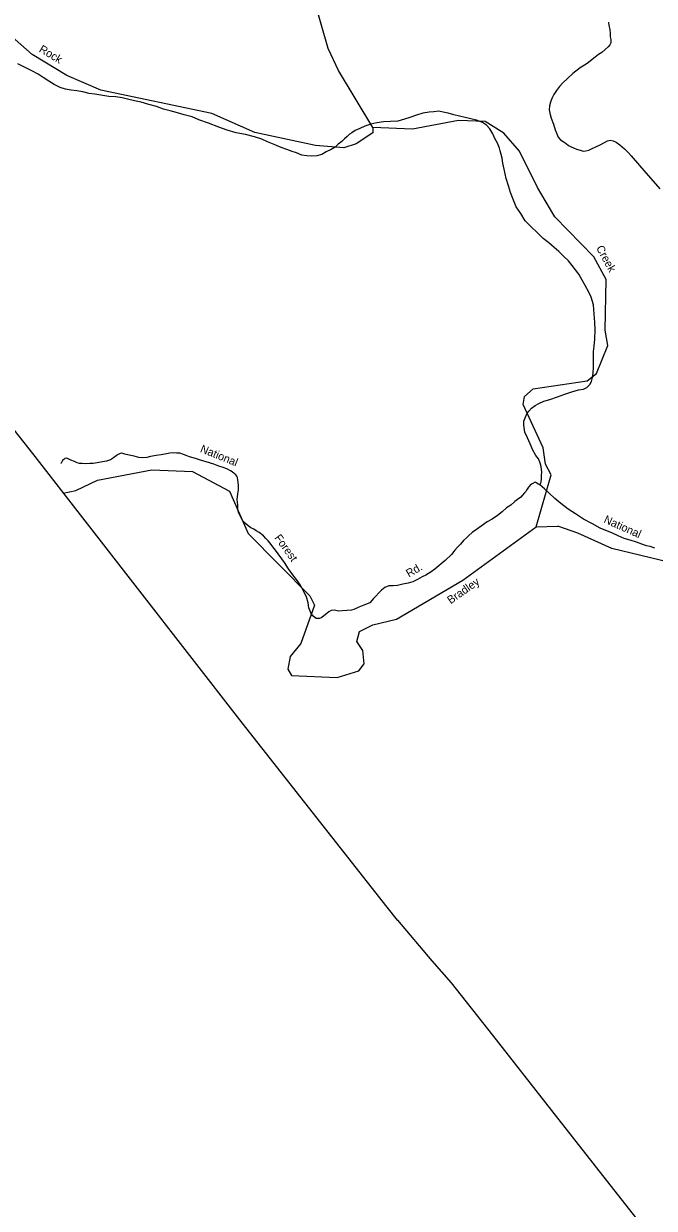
# Model space of a CAD drawing. Extents: x 884530 to 1028605, y 526725 to 653634.
# Drawn here: x 895600 to 900773, y 609593 to 619308 of the extents above; entities that cross this region are included whole.
import ezdxf

# ---------------------------------------------------------------- set-up
doc = ezdxf.new("R2010")
doc.units = 0
for name, color, linetype in [('Exist Boundary Political CountyLine', 7, 'Continuous'), ('Exist Hydrographic Creek Single Shore', 7, 'Continuous'), ('Exist Hydrographic Creek Single Shore Label', 7, 'Continuous'), ('Exist Hydrographic Misc Water Feature', 7, 'Continuous'), ('Exist Road Non-System Type 51', 7, 'Continuous'), ('Exist Road Secondary Type 51 Label', 7, 'Continuous'), ('Exist Road State Agency Type 41 National Forest', 7, 'Continuous')]:
    doc.layers.add(name, color=color, linetype=linetype)

msp = doc.modelspace()

# ---------------------------------------------------------------- linework, layer by layer
at = {"layer": 'Exist Boundary Political CountyLine'}
msp.add_lwpolyline([(884530.4, 629910.3), (884653.7, 629748.9), (884813.4, 629553.1), (885417.4, 628779.7), (886657.2, 627210), (887785.4, 625792.1), (888812.1, 624479.9), (890178.1, 622756.7), (890214.3, 622700.9), (890465.1, 622378.2), (892428, 619906.6), (893857.2, 618081), (895671, 615784.4), (897390.1, 613573.7), (898579.1, 612061.3), (898664.9, 611954.6), (898665.3, 611954.6), (898949, 611622.1), (899106.2, 611443), (899447, 611012.2), (899930.1, 610394.8), (900438.2, 609746.7), (902210.3, 607495.5)], dxfattribs=at)
at = {"layer": 'Exist Hydrographic Creek Single Shore'}
for points in [[(898465.1, 618456.6), (898463.7, 618413.9), (898326.6, 618321.5), (898225.5, 618290.7), (897992.7, 618308.5), (897496.4, 618416.9), (897143.6, 618571.7), (896233.3, 618763.8), (895954.4, 618884.3), (895668.8, 619054.1), (895483.1, 619218.6)], [(899802.8, 615181.9), (899927, 615608.4), (899880.2, 615694.7), (899860.4, 615829.6), (899698.2, 616184), (899709.3, 616249.4), (899778.2, 616313.7), (900222.7, 616380.2), (900299.7, 616437.8), (900391.8, 616668.9), (900371.3, 616794.1), (900378.5, 617210.6), (900277, 617396.4), (899955.7, 617724.5), (899814.4, 617963.5), (899667.1, 618261.8), (899539.1, 618408.8), (899384.4, 618507), (899167.7, 618514.6), (898789.9, 618443.5), (898465.1, 618456.6)], [(895924.1, 615459), (896028, 615480), (896206.3, 615565), (896651.3, 615647.9), (896984.3, 615634.7), (897286.9, 615474.4), (897441, 615126.7), (897947.3, 614614.5), (897986.1, 614538.3), (897874.5, 614225.5), (897787, 614118.9), (897766.5, 614014.4), (897798, 613961.3), (898172.6, 613947.1), (898349.6, 613999.4), (898393.5, 614057.6), (898380.9, 614166.1), (898333.6, 614242.5), (898353.5, 614324.1), (898463.8, 614377.7), (898657.2, 614423.1), (899202.8, 614743.5), (899802.8, 615181.9), (899982, 615187.2)], [(902911.8, 614462.4), (902755.5, 614527.9), (902511, 614680.5), (902374.1, 614807.9), (902276, 614862.4), (902083.3, 614836.7), (901772.2, 614990.6), (901628.8, 614944.3), (901447.9, 614793.7), (901437.7, 614744.7), (901256.1, 614567.9), (901131.5, 614580.2), (901010.3, 614684.3), (900901.2, 614890), (900424.7, 615002.6), (900145.3, 615129.2), (899982, 615187.2)]]:
    msp.add_lwpolyline(points, dxfattribs=at)
at = {"layer": 'Exist Hydrographic Misc Water Feature'}
msp.add_lwpolyline([(898465.1, 618456.6), (898182.3, 618924.9), (898097.3, 619103.9), (897934.9, 619668.2), (897896.5, 619987.3), (897919.4, 620603.7), (897871.1, 620870.5), (897795, 621065.6), (897412.2, 621539.3), (897312.3, 621767.7), (896946.4, 622247.6), (896395.3, 622901.8)], dxfattribs=at)
at = {"layer": 'Exist Road Non-System Type 51'}
for points in [[(900398.1, 619321.5), (900401.1, 619292.6), (900408, 619259.6), (900410, 619228.1), (900411.1, 619200.5), (900415.2, 619178.1)], [(900415.2, 619178.1), (900416, 619150.5), (900409.1, 619134.9), (900394, 619118.1), (900371.3, 619096.3), (900343.2, 619070.6), (900315.9, 619054.1), (900287, 619032.3), (900221, 618981.2), (900166.1, 618945.5), (900104.1, 618898.2), (900060, 618858.4), (900023.2, 618823.7), (899996, 618792.7), (899971.1, 618759.1), (899948.1, 618726.7), (899932, 618695.6), (899920.9, 618665.6), (899914.1, 618635.5), (899911.1, 618601.5), (899916.1, 618573.8), (899928.1, 618534.2), (899944.9, 618485.3), (899959, 618437.8), (899974.1, 618404.6), (899985.1, 618378.2), (900004, 618356.8), (900025, 618340.6), (900049, 618324.4), (900070, 618309.5), (900090.1, 618297.3), (900111.2, 618289), (900135, 618278), (900165, 618269.6), (900188.2, 618262.5), (900211.2, 618264.7), (900234.9, 618270.8), (900263.1, 618283.3), (900298.2, 618299.7), (900330, 618314.8), (900363.2, 618333.8), (900390, 618347.7), (900412.1, 618353.8), (900436, 618346.8), (900461, 618335.8), (900491.1, 618315.5), (900529.1, 618280.6), (900560.3, 618248.5), (900583.1, 618223.1), (900704.1, 618085.5), (900764.1, 618017.3), (900818.9, 617954.5)], [(898272.3, 618400.7), (898252.2, 618384), (898231.2, 618363.5), (898210.1, 618342.9), (898179.1, 618318.6), (898156, 618296.7), (898122.1, 618276.4), (898081, 618256.2), (898044.2, 618234.6), (898003.9, 618225), (897959.2, 618220.6), (897922.2, 618225.3), (897882.3, 618228.7), (897838, 618248), (897801.2, 618260.5), (897757.2, 618275.8), (897712.3, 618293.8), (897655, 618316), (897600.9, 618338), (897552.2, 618360), (897493.1, 618379.6), (897420, 618399.4), (897342.2, 618414.1), (897269.2, 618435.3), (897200.1, 618459), (897117, 618490.8), (897036.2, 618520), (896981.3, 618543.4), (896916.9, 618560.5), (896860.2, 618577.4), (896802.1, 618594.3), (896746.9, 618607.2), (896690.2, 618628), (896626.3, 618646.4), (896563, 618663.4), (896509.1, 618675), (896450, 618689.3), (896406.2, 618699.3), (896354.2, 618708.3), (896298.1, 618710.7), (896249.1, 618718.2), (896183, 618728.8), (896137.2, 618734.9), (896084.3, 618747.8), (896034.3, 618758), (895990.1, 618764.1), (895943.9, 618770.3), (895898.9, 618784.3), (895850.2, 618808.9), (895807.1, 618836), (895760.2, 618867.2), (895717.1, 618894.3), (895666.1, 618920.3), (895601.1, 618954.4), (895552.1, 618979)], [(899834.9, 615525), (899843.1, 615539.3), (899845, 615551), (899848.1, 615574.6), (899849, 615604.8), (899850.1, 615628.4), (899847.1, 615657.3), (899841.1, 615686.3), (899834.1, 615712.7), (899822.2, 615740.5), (899802, 615767.2), (899777, 615809.7), (899755.1, 615862.6), (899733.1, 615911.6), (899711.1, 615959.3), (899703, 616014.6), (899704, 616047.4), (899713.1, 616076.1), (899728.2, 616107.3), (899745, 616130.6), (899766.2, 616153.8), (899795.2, 616176.8), (899825, 616192), (899868.1, 616212.1), (899915, 616226.9), (899979.1, 616248), (900038.2, 616270.4), (900097, 616287.6), (900152.1, 616304.9), (900192, 616311.9), (900220.1, 616323.2), (900242.9, 616347.7), (900258.2, 616374.9), (900266.1, 616406.3), (900271.1, 616442.9), (900273, 616491.5), (900275.2, 616549.2), (900274.9, 616618.7), (900281.1, 616664.6), (900285.2, 616720.9), (900288, 616797), (900286, 616860), (900279.2, 616927.1), (900274.1, 617002), (900256, 617064.1), (900236.2, 617106.5), (900206.1, 617162.2), (900181, 617204.7), (900153.1, 617253.8), (900098.1, 617324.5), (900069, 617361.9), (900030.1, 617399.4), (899990.2, 617439.6), (899951.1, 617473.2), (899908.2, 617509.5), (899860.1, 617547.2), (899813.2, 617596.7), (899759, 617645), (899715, 617690.5), (899677.1, 617750.4), (899641.1, 617804.9), (899617, 617860.5), (899593, 617924), (899576.1, 617979.5), (899557.9, 618038.9), (899542, 618114), (899529.9, 618164.2), (899524.2, 618206.3), (899509.9, 618265.6), (899503.1, 618286.8), (899486, 618329.1), (899466, 618366.3), (899447.1, 618406), (899423, 618444.6), (899396, 618475.3), (899365, 618496.9), (899313.2, 618516.3), (899268.1, 618527.7), (899220.1, 618537.9), (899174, 618549.3), (899129, 618560.7), (899083, 618573.5), (899040.2, 618583.5), (899004.2, 618590.8), (898964.1, 618586.3), (898925, 618583.2), (898875.3, 618573.7), (898822.1, 618559), (898766.3, 618539.1), (898723.3, 618524.2), (898668.9, 618509.6), (898610.1, 618506.8), (898550.3, 618502.8), (898497.9, 618494.6), (898446.9, 618485.1), (898397, 618467.8), (898357.9, 618447.6), (898319.1, 618431.3), (898291.2, 618412.1), (898272.3, 618400.7)]]:
    msp.add_lwpolyline(points, dxfattribs=at)
at = {"layer": 'Exist Road State Agency Type 41 National Forest'}
for points in [[(897463.9, 615173.5), (897440, 615189.8), (897419, 615208.6), (897395.9, 615232.6), (897377.2, 615265.8), (897362.1, 615299), (897356.1, 615330.6), (897355.1, 615360.8), (897350.1, 615405.5), (897355.9, 615451.3), (897361.2, 615484), (897362.9, 615520.8), (897360.2, 615547.1), (897355.9, 615565.5), (897353.1, 615585.3), (897347.1, 615597.2), (897340.1, 615609.2), (897326.2, 615619.9), (897311, 615633.4), (897295.1, 615640.3), (897266.2, 615656.6), (897235.9, 615667.7), (897200.1, 615680.2), (897159.1, 615696.8), (897096.1, 615715.1), (897076.2, 615719.5), (897050.1, 615729.2), (897016.9, 615740.3), (896991.1, 615748.7), (896959.1, 615755.9), (896932.1, 615767), (896909.9, 615775.3), (896881.9, 615785.1), (896854.1, 615786.9), (896828.2, 615788.8), (896797.9, 615786.7), (896769.9, 615780.7), (896728.1, 615772.4), (896687, 615768), (896639.2, 615758.4), (896609.2, 615751.1), (896577.3, 615747.8), (896542.9, 615751.2), (896505, 615761.1), (896465.2, 615768.5), (896430.3, 615778.4), (896414, 615783.9), (896400.2, 615786.8), (896390, 615784.4), (896375.1, 615775.5), (896359.1, 615764), (896336.1, 615747.4), (896312.2, 615732.2), (896279.1, 615721), (896247.2, 615713.8), (896203.1, 615706.8), (896169.1, 615700.9), (896142.2, 615700.1), (896108.1, 615699.5), (896080.2, 615700.1), (896058.2, 615700.5), (896039, 615707.5), (896017.2, 615717.1), (895985.3, 615728.2), (895960.3, 615743.2), (895948.2, 615746), (895936, 615742.3), (895927.9, 615733.3), (895918.9, 615725.6), (895915.2, 615719.1), (895908, 615704.8), (895905.4, 615700.1)], [(900477.9, 615109.1), (900425.9, 615131.2), (900375.1, 615150.6), (900327.9, 615169.9), (900264.9, 615205.3), (900191.9, 615243.5), (900126.2, 615288.1), (900066.9, 615327.4), (900007.1, 615373.2), (899956.1, 615413.6), (899910, 615457.9), (899871.1, 615494.1), (899834.9, 615525), (899820.9, 615531.8), (899807.1, 615542.6), (899795, 615548.1), (899777.1, 615538), (899765.2, 615531.6), (899755.8, 615524), (899746.1, 615513.6), (899742, 615505.9), (899730.9, 615491.6), (899718, 615470.9), (899707.9, 615459.3), (899689.1, 615437.3), (899677, 615424.5), (899650.1, 615405.3), (899629.1, 615388.7), (899596, 615360.5), (899561.1, 615337.5), (899526, 615305.4), (899487, 615273.4), (899444.1, 615245.4), (899403.2, 615221.3), (899354, 615186.8), (899313.1, 615160.1), (899278.1, 615134.5), (899251.1, 615111.4), (899231.9, 615090.8), (899206.9, 615070.3), (899184, 615040.6), (899159.2, 615016.1), (899136, 614989), (899109.1, 614955.4), (899057.2, 614905.3), (898972.2, 614834.8), (898941.2, 614811.8), (898900, 614786.4), (898868.2, 614771.3), (898831, 614749.7), (898792.2, 614730.8), (898753.9, 614718.4), (898709.1, 614710.1), (898665, 614701.8), (898631.1, 614698.6), (898595, 614698), (898562.2, 614682.9), (898534.2, 614662.5), (898513.1, 614640.6), (898488, 614613.5), (898469.2, 614592.9), (898438, 614558.1), (898391, 614538), (898348, 614521.8), (898307.9, 614502.9), (898289.1, 614499.4), (898211.2, 614491.7), (898181, 614489.7), (898148.9, 614496.9), (898121, 614496.2), (898103.1, 614484.7), (898090.1, 614474.5), (898074, 614459.1), (898063, 614451.4), (898045.1, 614438.6), (898027.2, 614431.1), (898013.1, 614430.1), (897999.3, 614430.4), (897988.9, 614437.1), (897971.2, 614451.9), (897956.2, 614475.9), (897940, 614518.2), (897933, 614559), (897919.1, 614606.5), (897899, 614647.6), (897872.1, 614696.7), (897846, 614738), (897808, 614788.6), (897772.2, 614836.6), (897738.1, 614889.8), (897665, 614991), (897644.2, 615016.3), (897621.2, 615047), (897604.2, 615065.7), (897587.2, 615085.7), (897566, 615108.5), (897532.1, 615135.4), (897507.1, 615149), (897487, 615162.6), (897463.9, 615173.5)], [(900778.1, 615006), (900740, 615021.2), (900709, 615027.1), (900671.1, 615039.6), (900625.8, 615055), (900576, 615073), (900527.1, 615087.1), (900477.9, 615109.1)]]:
    msp.add_lwpolyline(points, dxfattribs=at)

# ---------------------------------------------------------------- texts
at = {"layer": 'Exist Hydrographic Creek Single Shore Label'}
for s, rotation, p in [('Rock', 329.26369, (895719.5, 619081.2)), ('Rock', 329.26369, (895719.5, 619081.2)), ('Creek', 298.65032, (900293.6, 617468.5)), ('Creek', 298.65032, (900293.6, 617468.5)), ('Bradley', 35.00269, (899102.4, 614546)), ('Bradley', 35.00269, (899102.4, 614546))]:
    msp.add_text(s, height=65.62, rotation=rotation, dxfattribs=at).set_placement(p)
at = {"layer": 'Exist Road Secondary Type 51 Label'}
for s, rotation, p in [('National', 337.99894, (897042.3, 615797)), ('National', 335.88073, (900353.2, 615218.9)), ('Forest', 305.84043, (897653.4, 615091.1)), ('Rd.', 30.11479, (898759.7, 614765.2))]:
    msp.add_text(s, height=65.62, rotation=rotation, dxfattribs=at).set_placement(p)

doc.saveas('drawing.dxf')
